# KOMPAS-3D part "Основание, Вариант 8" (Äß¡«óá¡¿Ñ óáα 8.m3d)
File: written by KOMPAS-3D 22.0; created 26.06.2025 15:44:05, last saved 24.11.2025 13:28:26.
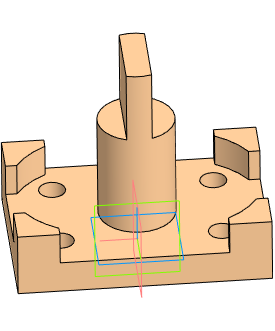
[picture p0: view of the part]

Document properties: Автор: Helen; Полное имя файла: C:\Для ноута\Инженерная графика\ППЭ 2025-2026\Варианты 1-38\Вариант 8 СБ\Вар 8 СБ\Основание вар 8.m3d

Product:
- Body: Тело 1
    Масса: 3.602917
- Part/product: Основание  | designation Вариант 8
    Масса: 3.587615

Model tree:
1. Эскиз:1
2. Элемент выдавливания:1
     Расстояние 1 = 20
3. Эскиз:2  (with: Элемент выдавливания:1)
4. Элемент выдавливания:2
     Расстояние 1 = 20
5. Зеркальный массив:1
6. Экземпляр ( 1 )
7. Экземпляр ( 2 )  (with: Элемент выдавливания:2)
8. Зеркальный массив:2  (with: Экземпляр ( 1 ), Экземпляр ( 2 ), Зеркальный массив:1, Элемент выдавливания:2)
9. Эскиз:3  (with: Элемент выдавливания:1)
10. Элемент выдавливания:3
11. Зеркальный массив:3  (with: Экземпляр ( 1 ), Экземпляр ( 2 ), Элемент выдавливания:3)
12. Зеркальный массив:4  (with: Экземпляр ( 1 ), Экземпляр ( 2 ), Зеркальный массив:3, Элемент выдавливания:3)
13. Эскиз:6  (with: Элемент выдавливания:1)
14. Элемент выдавливания:6
     Расстояние 1 = 65
15. Эскиз:7  (with: Элемент выдавливания:6)
16. Элемент выдавливания:7
     Расстояние 1 = 45

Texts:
  Вариант 8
